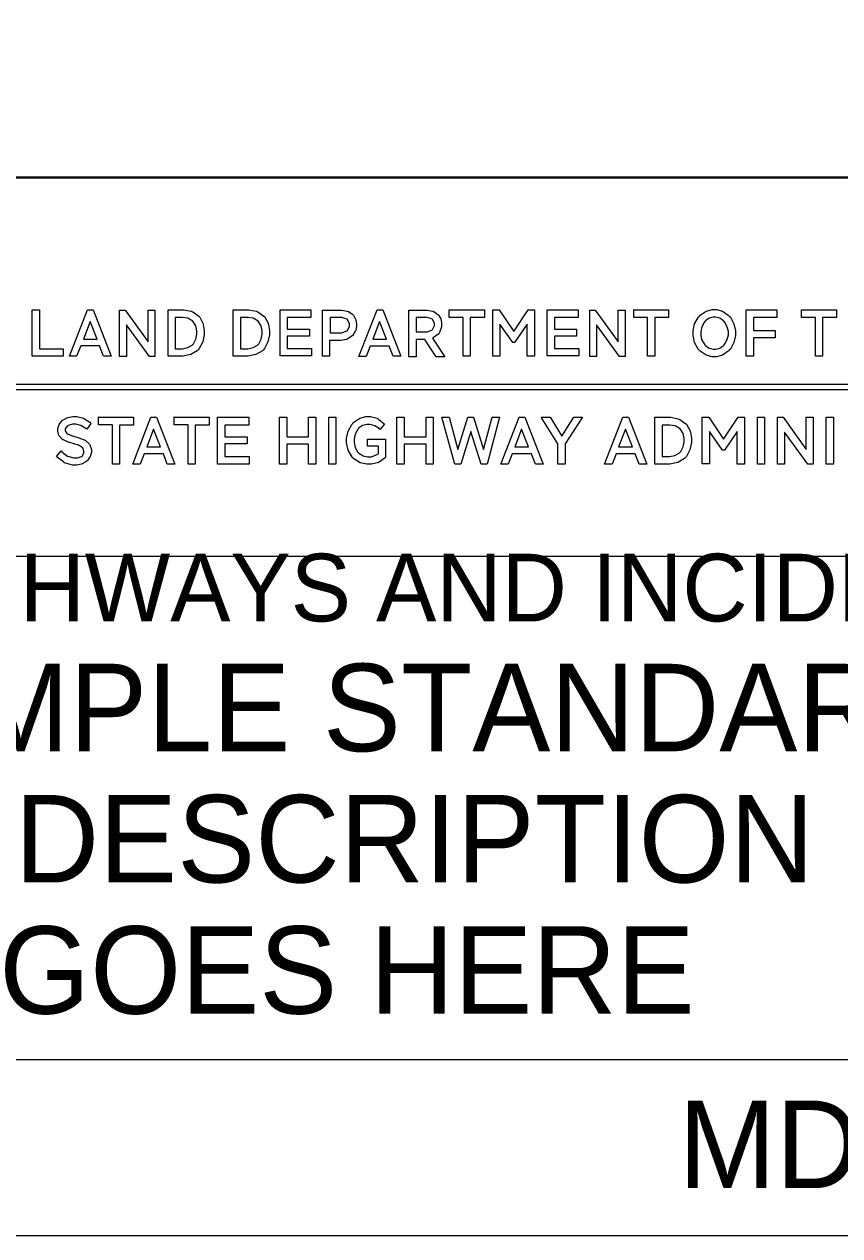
# Model space of a CAD drawing. Extents: x -0.5 to 19.9, y 5.2 to 17.3.
# Drawn here: x 5.013 to 6.132, y 5.937 to 7.599 of the extents above; entities that cross this region are included whole.
import ezdxf

# ---------------------------------------------------------------- set-up
doc = ezdxf.new("R2010")
doc.units = 0
for name, color, linetype in [('BORD-LINE', 7, 'Continuous'), ('DETL-NOTE', 7, 'Continuous'), ('MSHA-LOGO', 7, 'Continuous'), ('TTLB-TEXT', 7, 'Continuous'), ('USER-BORD', 7, 'Continuous'), ('USER-LINE', 7, 'Continuous')]:
    doc.layers.add(name, color=color, linetype=linetype)

msp = doc.modelspace()

# ---------------------------------------------------------------- linework, layer by layer
at = {"layer": 'BORD-LINE'}
msp.add_line((7.7685, 7.3883), (0.3943, 7.3883), dxfattribs=at)
at = {"layer": 'MSHA-LOGO'}
for points in [[(5.024, 7.2075), (5.0338, 7.2075), (5.0338, 7.1542), (5.0662, 7.1542), (5.0662, 7.144), (5.024, 7.144)], [(5.0999, 7.2075), (5.1074, 7.2075), (5.1323, 7.144), (5.1218, 7.144), (5.1162, 7.1582), (5.0904, 7.1582), (5.0848, 7.144), (5.075, 7.144)], [(5.1846, 7.1437), (5.1532, 7.1871), (5.1532, 7.1437), (5.1437, 7.1437), (5.1437, 7.2072), (5.1513, 7.2072), (5.1827, 7.1638), (5.1827, 7.2072), (5.1922, 7.2072), (5.1922, 7.1437)], [(5.2102, 7.2075), (5.2278, 7.2075), (5.2316, 7.2075), (5.2418, 7.2056), (5.2429, 7.2052), (5.244, 7.2048), (5.2524, 7.199), (5.253, 7.1983), (5.2536, 7.1976), (5.258, 7.1893), (5.2583, 7.1884), (5.2585, 7.1875), (5.2599, 7.1793), (5.2599, 7.1766), (5.2599, 7.1733), (5.2579, 7.1635), (5.2531, 7.1545), (5.2517, 7.1529), (5.2503, 7.1514), (5.2414, 7.1462), (5.2305, 7.144), (5.2269, 7.144), (5.2102, 7.144)], [(5.22, 7.197), (5.22, 7.1542), (5.2275, 7.1542), (5.23, 7.1542), (5.2373, 7.1557), (5.2433, 7.1591), (5.2442, 7.1601), (5.2451, 7.1611), (5.2483, 7.1672), (5.2498, 7.1742), (5.2498, 7.1766), (5.2498, 7.1789), (5.2484, 7.1857), (5.2443, 7.1921), (5.2375, 7.196), (5.2302, 7.1973), (5.2278, 7.1973), (5.22, 7.1973)], [(5.2995, 7.2075), (5.3172, 7.2075), (5.3209, 7.2075), (5.3312, 7.2056), (5.3322, 7.2052), (5.3333, 7.2048), (5.3417, 7.199), (5.3424, 7.1983), (5.3429, 7.1976), (5.3474, 7.1893), (5.3476, 7.1884), (5.3479, 7.1875), (5.3493, 7.1793), (5.3493, 7.1766), (5.3493, 7.1733), (5.3472, 7.1635), (5.3425, 7.1545), (5.3411, 7.1529), (5.3397, 7.1514), (5.3307, 7.1462), (5.3198, 7.144), (5.3162, 7.144), (5.2995, 7.144)], [(5.3096, 7.197), (5.3096, 7.1542), (5.3172, 7.1542), (5.3196, 7.1542), (5.327, 7.1557), (5.333, 7.1591), (5.3339, 7.1601), (5.3348, 7.1611), (5.338, 7.1672), (5.3394, 7.1742), (5.3394, 7.1766), (5.3394, 7.1789), (5.3381, 7.1857), (5.334, 7.1921), (5.3271, 7.196), (5.3199, 7.1973), (5.3175, 7.1973), (5.3096, 7.1973)], [(5.364, 7.2075), (5.4062, 7.2075), (5.4062, 7.1973), (5.3738, 7.1973), (5.3738, 7.1812), (5.4042, 7.1812), (5.4042, 7.1713), (5.3738, 7.1713), (5.3738, 7.1545), (5.4072, 7.1545), (5.4072, 7.1443), (5.364, 7.1443)], [(5.4222, 7.1437), (5.4222, 7.2072), (5.4451, 7.2072), (5.4481, 7.2072), (5.4561, 7.2058), (5.4569, 7.2055), (5.4577, 7.2052), (5.4637, 7.2011), (5.4641, 7.2006), (5.4645, 7.2001), (5.4675, 7.1946), (5.4677, 7.194), (5.4679, 7.1934), (5.4687, 7.1882), (5.4687, 7.1864), (5.4687, 7.1846), (5.4676, 7.1795), (5.4674, 7.1789), (5.4671, 7.1783), (5.4639, 7.1728), (5.4635, 7.1723), (5.463, 7.1718), (5.4568, 7.1677), (5.4559, 7.1674), (5.4551, 7.167), (5.4474, 7.1657), (5.4448, 7.1657), (5.4317, 7.1657), (5.4317, 7.144), (5.4222, 7.144)], [(5.4324, 7.1973), (5.4324, 7.1759), (5.4455, 7.1759), (5.448, 7.1759), (5.4558, 7.1786), (5.4592, 7.1848), (5.4592, 7.1868), (5.4592, 7.1888), (5.456, 7.1946), (5.4486, 7.1973), (5.4461, 7.1973)], [(5.4972, 7.2075), (5.5047, 7.2075), (5.5296, 7.144), (5.5191, 7.144), (5.5135, 7.1578), (5.4877, 7.1578), (5.4821, 7.1437), (5.472, 7.1437)], [(5.5407, 7.1437), (5.5407, 7.2072), (5.5629, 7.2072), (5.5657, 7.2072), (5.5733, 7.2058), (5.5741, 7.2055), (5.5748, 7.2053), (5.5805, 7.2014), (5.5809, 7.2009), (5.5814, 7.2004), (5.5843, 7.1952), (5.5845, 7.1947), (5.5847, 7.1941), (5.5855, 7.1889), (5.5855, 7.1871), (5.5855, 7.1842), (5.5828, 7.1764), (5.5823, 7.1756), (5.5817, 7.1748), (5.5741, 7.169), (5.5731, 7.1687), (5.5901, 7.1433), (5.578, 7.1433), (5.5626, 7.1667), (5.5505, 7.1667), (5.5505, 7.1433), (5.5407, 7.1433)], [(5.5508, 7.197), (5.5508, 7.1776), (5.5636, 7.1776), (5.5658, 7.1776), (5.5719, 7.1798), (5.5724, 7.1802), (5.5729, 7.1806), (5.5757, 7.186), (5.5757, 7.1878), (5.5757, 7.1895), (5.5732, 7.1943), (5.5728, 7.1947), (5.5723, 7.1951), (5.5655, 7.197), (5.5633, 7.197)], [(5.596, 7.2075), (5.6441, 7.2075), (5.6441, 7.1973), (5.6248, 7.1973), (5.6248, 7.144), (5.615, 7.144), (5.615, 7.1973), (5.596, 7.1973)], [(5.6556, 7.2075), (5.6644, 7.2075), (5.6847, 7.1779), (5.7043, 7.2075), (5.7128, 7.2075), (5.7128, 7.144), (5.703, 7.144), (5.703, 7.1881), (5.6857, 7.1628), (5.6831, 7.1628), (5.6654, 7.1881), (5.6654, 7.144), (5.6556, 7.144)], [(5.7305, 7.2075), (5.7727, 7.2075), (5.7727, 7.1973), (5.7403, 7.1973), (5.7403, 7.1812), (5.7707, 7.1812), (5.7707, 7.1713), (5.7403, 7.1713), (5.7403, 7.1545), (5.7737, 7.1545), (5.7737, 7.1443), (5.7305, 7.1443)], [(5.8297, 7.1437), (5.7982, 7.1871), (5.7982, 7.1437), (5.7887, 7.1437), (5.7887, 7.2072), (5.7963, 7.2072), (5.8277, 7.1638), (5.8277, 7.2072), (5.8372, 7.2072), (5.8372, 7.1437)], [(5.8486, 7.2075), (5.8967, 7.2075), (5.8967, 7.1973), (5.8778, 7.1973), (5.8778, 7.144), (5.868, 7.144), (5.868, 7.1973), (5.849, 7.1973), (5.849, 7.2075)], [(5.9389, 7.1986), (5.9403, 7.2002), (5.9482, 7.2057), (5.9567, 7.2082), (5.9595, 7.2082), (5.9624, 7.2082), (5.9708, 7.2059), (5.9788, 7.2005), (5.9802, 7.199), (5.9816, 7.1974), (5.9865, 7.1885), (5.9887, 7.1788), (5.9887, 7.1756), (5.9887, 7.1724), (5.9865, 7.1628), (5.9816, 7.1538), (5.9802, 7.1522), (5.9788, 7.1507), (5.9708, 7.1453), (5.9624, 7.143), (5.9595, 7.143), (5.9567, 7.143), (5.9482, 7.1453), (5.9403, 7.1507), (5.9389, 7.1522), (5.9375, 7.1538), (5.9326, 7.1627), (5.9304, 7.1724), (5.9304, 7.1756), (5.9304, 7.1788), (5.9326, 7.1882), (5.9375, 7.1971)], [(5.9465, 7.1598), (5.9474, 7.1587), (5.9526, 7.1551), (5.958, 7.1536), (5.9599, 7.1536), (5.9617, 7.1536), (5.9672, 7.1551), (5.9724, 7.1587), (5.9733, 7.1598), (5.9742, 7.1608), (5.9774, 7.1667), (5.9789, 7.1734), (5.9789, 7.1756), (5.9789, 7.1778), (5.9774, 7.1845), (5.9742, 7.1904), (5.9733, 7.1914), (5.9724, 7.1925), (5.9672, 7.1961), (5.9617, 7.1976), (5.9599, 7.1976), (5.958, 7.1976), (5.9526, 7.1961), (5.9474, 7.1925), (5.9465, 7.1914), (5.9456, 7.1904), (5.9423, 7.1845), (5.9409, 7.1778), (5.9409, 7.1756), (5.9409, 7.1734), (5.9422, 7.1667), (5.9455, 7.1608)], [(6.0034, 7.2075), (6.0453, 7.2075), (6.0453, 7.1973), (6.0132, 7.1973), (6.0132, 7.1792), (6.043, 7.1792), (6.043, 7.169), (6.0132, 7.169), (6.0132, 7.144), (6.0034, 7.144)], [(6.079, 7.2075), (6.1271, 7.2075), (6.1271, 7.1973), (6.1081, 7.1973), (6.1081, 7.144), (6.0983, 7.144), (6.0983, 7.1973), (6.0793, 7.1973), (6.0793, 7.2075)], [(5.0943, 7.1674), (5.113, 7.1674), (5.1035, 7.1914)], [(5.4913, 7.1674), (5.5099, 7.1674), (5.5004, 7.1914)], [(4.7668, 7.1057), (6.8835, 7.1057), (6.8835, 7.0979), (4.7668, 7.0979)], [(5.0929, 7.0185), (5.0926, 7.0188), (5.0883, 7.0214), (5.0878, 7.0217), (5.0872, 7.0218), (5.0814, 7.0238), (5.0807, 7.0239), (5.0801, 7.0241), (5.0737, 7.0259), (5.0731, 7.0262), (5.0724, 7.0264), (5.0666, 7.0291), (5.066, 7.0294), (5.0655, 7.0297), (5.0613, 7.0343), (5.0609, 7.0348), (5.0606, 7.0354), (5.059, 7.0413), (5.059, 7.0432), (5.059, 7.0449), (5.0607, 7.0502), (5.0644, 7.0552), (5.0654, 7.056), (5.0664, 7.0569), (5.0726, 7.0599), (5.0794, 7.0612), (5.0817, 7.0612), (5.0849, 7.0612), (5.0944, 7.0588), (5.1027, 7.0534), (5.1041, 7.0519), (5.0986, 7.0438), (5.0974, 7.045), (5.0907, 7.0489), (5.0837, 7.0506), (5.0814, 7.0506), (5.0792, 7.0506), (5.0733, 7.049), (5.0728, 7.0486), (5.0722, 7.0483), (5.0692, 7.0442), (5.0692, 7.0429), (5.0692, 7.0416), (5.0714, 7.0381), (5.0718, 7.0377), (5.0722, 7.0374), (5.0778, 7.035), (5.0785, 7.0348), (5.0792, 7.0347), (5.0863, 7.0325), (5.0871, 7.0323), (5.0879, 7.032), (5.0951, 7.0293), (5.0958, 7.0291), (5.0964, 7.0287), (5.102, 7.0239), (5.1025, 7.0233), (5.1029, 7.0226), (5.105, 7.0161), (5.105, 7.014), (5.105, 7.0121), (5.1034, 7.0063), (5.0997, 7.001), (5.0986, 7.0002), (5.0976, 6.9993), (5.0915, 6.9961), (5.0851, 6.9947), (5.083, 6.9947), (5.0793, 6.9947), (5.0695, 6.9974), (5.0683, 6.9979), (5.0671, 6.9985), (5.0581, 7.0055), (5.0574, 7.0063), (5.0635, 7.014), (5.0648, 7.0125), (5.0724, 7.007), (5.081, 7.0047), (5.0839, 7.0047), (5.0859, 7.0047), (5.0914, 7.0063), (5.0919, 7.0066), (5.0924, 7.0069), (5.0948, 7.011), (5.0948, 7.0124), (5.0948, 7.0139), (5.0932, 7.0181)], [(5.1143, 7.0602), (5.1629, 7.0602), (5.1629, 7.0496), (5.1437, 7.0496), (5.1437, 6.996), (5.1338, 6.996), (5.1338, 7.0499), (5.1146, 7.0499), (5.1146, 7.0602)], [(5.1868, 7.0602), (5.1945, 7.0602), (5.2197, 6.996), (5.2092, 6.996), (5.2038, 7.0101), (5.1776, 7.0101), (5.1721, 6.996), (5.1619, 6.996)], [(5.2181, 7.0602), (5.2667, 7.0602), (5.2667, 7.0496), (5.2475, 7.0496), (5.2475, 6.996), (5.2376, 6.996), (5.2376, 7.0499), (5.2185, 7.0499), (5.2185, 7.0602)], [(5.2782, 7.0602), (5.321, 7.0602), (5.321, 7.0496), (5.2881, 7.0496), (5.2881, 7.0336), (5.3188, 7.0336), (5.3188, 7.0236), (5.2881, 7.0236), (5.2881, 7.0066), (5.3217, 7.0066), (5.3217, 6.996), (5.2782, 6.996)], [(5.4031, 7.0233), (5.3731, 7.0233), (5.3731, 6.996), (5.3632, 6.996), (5.3632, 7.0602), (5.3731, 7.0602), (5.3731, 7.0336), (5.4031, 7.0336), (5.4031, 7.0602), (5.413, 7.0602), (5.413, 6.996), (5.4031, 6.996)], [(5.4306, 7.0602), (5.4405, 7.0602), (5.4405, 6.996), (5.4306, 6.996)], [(5.4837, 7.0303), (5.5086, 7.0303), (5.5086, 7.0056), (5.5079, 7.0048), (5.4996, 6.9986), (5.4987, 6.9982), (5.4976, 6.9978), (5.4888, 6.9957), (5.4859, 6.9957), (5.4828, 6.9957), (5.4737, 6.9979), (5.4653, 7.0031), (5.4638, 7.0047), (5.4624, 7.0062), (5.4574, 7.0151), (5.4552, 7.0251), (5.4552, 7.0284), (5.4552, 7.0316), (5.4573, 7.0412), (5.4622, 7.0503), (5.4635, 7.0519), (5.465, 7.0535), (5.4731, 7.0589), (5.4817, 7.0612), (5.4846, 7.0612), (5.4879, 7.0612), (5.497, 7.0588), (5.498, 7.0583), (5.499, 7.0578), (5.5067, 7.0514), (5.5073, 7.0506), (5.5006, 7.0435), (5.4997, 7.0446), (5.4941, 7.0486), (5.4875, 7.0503), (5.4853, 7.0503), (5.4832, 7.0503), (5.4771, 7.0488), (5.4717, 7.0452), (5.4709, 7.0441), (5.47, 7.0432), (5.4668, 7.0372), (5.4654, 7.0304), (5.4654, 7.0281), (5.4654, 7.0258), (5.4669, 7.0188), (5.4702, 7.0128), (5.4712, 7.0117), (5.4721, 7.0108), (5.4777, 7.0074), (5.4838, 7.0059), (5.4859, 7.0059), (5.4891, 7.0059), (5.4981, 7.0097), (5.499, 7.0104), (5.499, 7.0204), (5.4837, 7.0204)], [(5.5642, 7.0233), (5.5341, 7.0233), (5.5341, 6.996), (5.5242, 6.996), (5.5242, 7.0602), (5.5341, 7.0602), (5.5341, 7.0336), (5.5642, 7.0336), (5.5642, 7.0602), (5.5741, 7.0602), (5.5741, 6.996), (5.5642, 6.996)], [(5.6479, 6.996), (5.6396, 6.996), (5.6255, 7.0406), (5.6118, 6.996), (5.6035, 6.996), (5.5856, 7.0602), (5.5958, 7.0602), (5.6079, 7.0159), (5.6214, 7.0602), (5.6294, 7.0602), (5.6431, 7.0159), (5.6549, 7.0602), (5.6648, 7.0602)], [(5.692, 7.0602), (5.6996, 7.0602), (5.7249, 6.996), (5.7143, 6.996), (5.7086, 7.0101), (5.6824, 7.0101), (5.677, 6.996), (5.6667, 6.996)], [(5.7549, 7.0239), (5.7549, 6.996), (5.745, 6.996), (5.745, 7.0239), (5.722, 7.0602), (5.7345, 7.0602), (5.7504, 7.0345), (5.7667, 7.0602), (5.7786, 7.0602)], [(5.8341, 7.0602), (5.8417, 7.0602), (5.867, 6.996), (5.8564, 6.996), (5.851, 7.0101), (5.8248, 7.0101), (5.8193, 6.996), (5.8091, 6.996)], [(5.8781, 7.0602), (5.896, 7.0602), (5.8998, 7.0602), (5.91, 7.058), (5.9111, 7.0576), (5.9121, 7.0572), (5.9206, 7.0514), (5.9213, 7.0506), (5.9219, 7.0498), (5.9264, 7.0416), (5.9267, 7.0406), (5.927, 7.0397), (5.9283, 7.0315), (5.9283, 7.0287), (5.9283, 7.0254), (5.9262, 7.0155), (5.9213, 7.0065), (5.92, 7.005), (5.9186, 7.0035), (5.9096, 6.9982), (5.8987, 6.996), (5.8951, 6.996), (5.8781, 6.996)], [(5.888, 7.0496), (5.888, 7.0063), (5.8957, 7.0063), (5.8982, 7.0063), (5.9056, 7.0078), (5.9117, 7.0113), (5.9127, 7.0124), (5.9136, 7.0134), (5.9168, 7.0196), (5.9181, 7.0265), (5.9181, 7.0287), (5.9181, 7.031), (5.9167, 7.0378), (5.9126, 7.0444), (5.9057, 7.0483), (5.8984, 7.0496), (5.896, 7.0496)], [(5.943, 7.0602), (5.9519, 7.0602), (5.9724, 7.0303), (5.9922, 7.0602), (6.0008, 7.0602), (6.0008, 6.996), (5.9909, 6.996), (5.9909, 7.0406), (5.9734, 7.0152), (5.9708, 7.0152), (5.9529, 7.0409), (5.9529, 6.9963), (5.943, 6.9963)], [(6.0187, 7.0602), (6.0286, 7.0602), (6.0286, 6.996), (6.0187, 6.996)], [(6.0877, 6.996), (6.0561, 7.0397), (6.0561, 6.996), (6.0465, 6.996), (6.0465, 7.0602), (6.0542, 7.0602), (6.0858, 7.0162), (6.0858, 7.0602), (6.0954, 7.0602), (6.0954, 6.996)], [(6.113, 7.0602), (6.1229, 7.0602), (6.1229, 6.996), (6.113, 6.996)], [(5.1811, 7.0197), (5.1999, 7.0197), (5.1903, 7.0441)], [(5.6859, 7.0197), (5.7048, 7.0197), (5.6952, 7.0441)], [(5.8283, 7.0197), (5.8472, 7.0197), (5.8376, 7.0441)]]:
    msp.add_lwpolyline(points, close=True, dxfattribs=at)
at = {"layer": 'TTLB-TEXT'}
msp.add_line((7.7685, 7.3883), (0.3943, 7.3883), dxfattribs=at)
msp.add_lwpolyline([(0.3943, 16.2906), (7.7685, 16.2906), (7.7685, 5.9375), (0.3943, 5.9375)], close=True, dxfattribs=at)
at = {"layer": 'USER-BORD'}
for p, q in [((7.7685, 7.3883), (0.3943, 7.3883)), ((3.2956, 6.1793), (7.7685, 6.1793))]:
    msp.add_line(p, q, dxfattribs=at)
at = {"layer": 'USER-LINE'}
msp.add_lwpolyline([(7.0197, 6.8692), (4.0486, 6.8692), (4.0486, 7.3899), (7.0197, 7.3899)], close=True, dxfattribs=at)

# ---------------------------------------------------------------- texts
at = {"layer": 'DETL-NOTE'}
msp.add_text('STANDARDS FOR HIGHWAYS AND INCIDENTAL STRUCTURES', height=0.09269, dxfattribs=at).set_placement((3.6914, 6.7803))
at = {"layer": 'TTLB-TEXT'}
for s, height, p in [('STANDARDS FOR HIGHWAYS AND INCIDENTAL STRUCTURES', 0.09269, (3.6913, 6.7802)), ('STANDARDS FOR HIGHWAYS AND INCIDENTAL STRUCTURES', 0.09269, (3.6914, 6.7803)), ('SAMPLE STANDARD', 0.12, (4.727, 6.6021)), ('DESCRIPTION', 0.12, (4.9998, 6.4221)), ('GOES HERE  ', 0.12, (4.9786, 6.2421)), ('MD 000.00', 0.12, (5.9104, 6.0029))]:
    msp.add_text(s, height=height, dxfattribs=at).set_placement(p)

doc.saveas('drawing.dxf')
